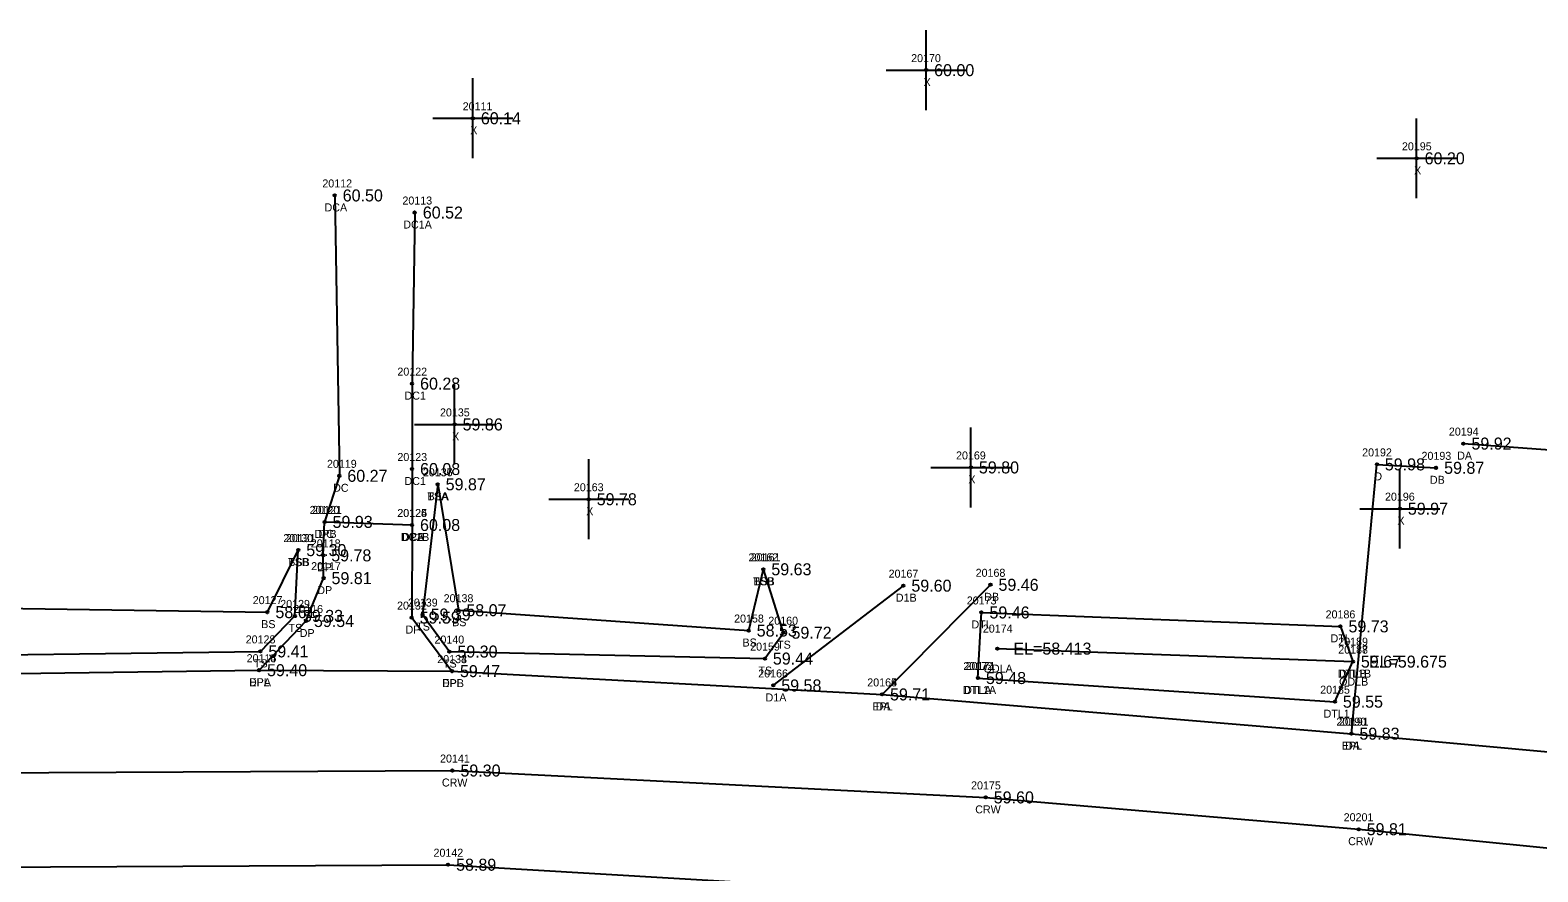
# Model space of a CAD drawing. Extents: x 2420351 to 2422725, y 845330 to 846558.
# Drawn here: x 2420630.1 to 2420818.7, y 845710.4 to 845815.6 of the extents above; entities that cross this region are included whole.
import ezdxf

# ---------------------------------------------------------------- set-up
doc = ezdxf.new("R2010")
doc.units = 0
for name, color, linetype in [('RD_DTM_BkLn1', 7, 'Continuous'), ('RD_DTM_BkLn2', 7, 'Continuous'), ('RD_DTM_BkLn_txCode', 7, 'Continuous'), ('RD_EX_Conc', 7, 'Continuous'), ('RD_EX_Conc_txCode', 7, 'Continuous'), ('RD_EX_Driveway', 7, 'Continuous'), ('RD_EX_Driveway_txCode', 7, 'Continuous'), ('RD_EX_H2O', 7, 'Continuous'), ('RD_EX_H2O_txCode', 7, 'Continuous'), ('RD_EX_Misc', 7, 'Continuous'), ('RD_EX_Misc_txCode', 7, 'Continuous'), ('RD_EX_Road', 7, 'Continuous'), ('RD_EX_Road_txCode', 7, 'Continuous'), ('RD_EX_TX_Conc_ELEV', 7, 'Continuous'), ('RD_EX_TX_Driveway_ELEV', 7, 'Continuous'), ('RD_EX_TX_H2O_ELEV', 7, 'Continuous'), ('RD_EX_TX_Misc_ELEV', 7, 'Continuous'), ('RD_EX_TX_Road_ELEV', 7, 'Continuous'), ('RD_HC_Survey_ELEV', 7, 'Continuous'), ('RD_HC_Survey_txCode', 7, 'Continuous'), ('RD_SMD_Locator', 7, 'Continuous')]:
    doc.layers.add(name, color=color, linetype=linetype)

msp = doc.modelspace()

# ---------------------------------------------------------------- linework, layer by layer
at = {"layer": 'RD_DTM_BkLn1'}
msp.add_lwpolyline([(2420378.71, 845690.53), (2420439.5, 845704.09), (2420489.95, 845712.49), (2420551.89, 845719.42), (2420551.95, 845719.57), (2420607.12, 845722.67), (2420682.92, 845723.04), (2420749.65, 845719.68), (2420796.31, 845715.7), (2420900.74, 845705.33), (2421018.16, 845694.11), (2421114.61, 845684.8), (2421175.74, 845680.1), (2421234.97, 845678.35), (2421292.42, 845679.46), (2421350.56, 845683.65), (2421414.53, 845692.12), (2421472.54, 845703.63), (2421533.08, 845718.31), (2421555.4, 845725.02), (2421609.81, 845741.71), (2421666.58, 845762.88), (2421744.67, 845798.22)], dxfattribs=at)
at = {"layer": 'RD_DTM_BkLn2'}
for points in [[(2420681.07, 845758.84), (2420679.19, 845742.55), (2420682.54, 845737.92), (2420722.01, 845737.04), (2420724.34, 845740.28), (2420721.82, 845748.21)], [(2420681.07, 845758.84), (2420683.66, 845743.09), (2420719.99, 845740.55), (2420721.82, 845748.21)], [(2420486.29, 845740.93), (2420484.7, 845732.95), (2420489.01, 845728.47), (2420550.73, 845734.95), (2420607.11, 845737.26), (2420658.89, 845737.94), (2420663.21, 845742.38), (2420663.63, 845750.61)], [(2420486.29, 845740.93), (2420490.14, 845734.65), (2420550.02, 845741.87), (2420606.87, 845743.63), (2420659.77, 845742.85), (2420663.63, 845750.61)]]:
    msp.add_lwpolyline(points, dxfattribs=at)
at = {"layer": 'RD_EX_Conc'}
for points in [[(2420668.19, 845794.97), (2420668.77, 845759.9), (2420666.92, 845754.14), (2420677.86, 845753.75)], [(2420678.21, 845792.83), (2420677.87, 845771.43), (2420677.87, 845760.75), (2420677.86, 845753.75)]]:
    msp.add_lwpolyline(points, dxfattribs=at)
at = {"layer": 'RD_EX_Driveway'}
for p, q in [((2420723.06, 845733.68), (2420739.34, 845746.16)), ((2420736.67, 845732.56), (2420750.24, 845746.27))]:
    msp.add_line(p, q, dxfattribs=at)
for points in [[(2420809.42, 845763.93), (2420862.38, 845760.08), (2420865.05, 845760.09), (2420893.89, 845756.85), (2420889.7, 845718.98)], [(2420795.4, 845727.65), (2420798.58, 845761.33), (2420806, 845760.9)], [(2420658.72, 845735.59), (2420664.59, 845741.74), (2420666.79, 845747.1), (2420666.75, 845749.95), (2420666.92, 845754.14)], [(2420677.86, 845753.75), (2420677.82, 845742.17), (2420682.86, 845735.47)]]:
    msp.add_lwpolyline(points, dxfattribs=at)
at = {"layer": 'RD_EX_H2O'}
msp.add_line((2420751.11, 845738.29), (2420795.58, 845736.66), dxfattribs=at)
for points in [[(2420748.67, 845734.61), (2420749.11, 845742.81), (2420794.03, 845741.07), (2420795.58, 845736.66)], [(2420748.67, 845734.61), (2420793.33, 845731.65), (2420795.58, 845736.66)]]:
    msp.add_lwpolyline(points, dxfattribs=at)
at = {"layer": 'RD_EX_Misc'}
for p, q in [((2420742.19, 845805.64), (2420742.19, 845815.64)), ((2420737.19, 845810.64), (2420747.19, 845810.64)), ((2420685.47, 845799.62), (2420685.47, 845809.62)), ((2420680.47, 845804.62), (2420690.47, 845804.62)), ((2420803.56, 845794.61), (2420803.56, 845804.61)), ((2420798.56, 845799.61), (2420808.56, 845799.61)), ((2420683.19, 845761.33), (2420683.19, 845771.33)), ((2420678.19, 845766.33), (2420688.19, 845766.33)), ((2420747.79, 845755.95), (2420747.79, 845765.95)), ((2420699.97, 845751.97), (2420699.97, 845761.97)), ((2420742.79, 845760.95), (2420752.79, 845760.95)), ((2420801.46, 845750.79), (2420801.46, 845760.79)), ((2420694.97, 845756.97), (2420704.97, 845756.97)), ((2420796.46, 845755.79), (2420806.46, 845755.79))]:
    msp.add_line(p, q, dxfattribs=at)
at = {"layer": 'RD_EX_Road'}
for points in [[(2420388.28, 845680.39), (2420441.29, 845692.04), (2420492.62, 845700.7), (2420553.92, 845707.41), (2420607.69, 845710.85), (2420682.38, 845711.26), (2420749.44, 845707.27), (2420795.12, 845703.44), (2420900.28, 845693.42), (2421017.17, 845682.19), (2421113.9, 845672.97), (2421174.87, 845668.16), (2421234.59, 845666.13), (2421293, 845667.25), (2421351.24, 845671.5), (2421419.82, 845681.17), (2421463.19, 845688.63), (2421558.82, 845713.18), (2421614.57, 845730.45), (2421670.73, 845751.42), (2421735.61, 845780.5), (2421750.75, 845787.87), (2421744.67, 845798.22), (2421739.21, 845808.11)], [(2420376.35, 845701.93), (2420403.68, 845709.11), (2420436.45, 845715.41), (2420465.85, 845720.8), (2420487.58, 845724.76), (2420551.29, 845731.53), (2420607.05, 845734.89), (2420658.72, 845735.59), (2420682.86, 845735.47), (2420736.67, 845732.56), (2420795.4, 845727.65), (2420889.7, 845718.98), (2420911.08, 845716.87), (2420953.91, 845713.71), (2420998.34, 845708.25), (2421018.47, 845706.55), (2421116.02, 845696.98), (2421176.98, 845692), (2421235.85, 845690.14), (2421292.32, 845691.44), (2421350.22, 845695.49), (2421412.35, 845704.28)]]:
    msp.add_lwpolyline(points, dxfattribs=at)
at = {"layer": 'RD_SMD_Locator'}
for centre in [(2420742.19, 845810.64), (2420685.47, 845804.62), (2420803.56, 845799.61), (2420668.19, 845794.97), (2420678.21, 845792.83), (2420677.87, 845771.43), (2420683.19, 845766.33), (2420809.42, 845763.93), (2420668.77, 845759.9), (2420677.87, 845760.75), (2420747.79, 845760.95), (2420798.58, 845761.33), (2420806, 845760.9), (2420681.07, 845758.84), (2420681.07, 845758.84), (2420699.97, 845756.97), (2420801.46, 845755.79), (2420666.92, 845754.14), (2420666.92, 845754.14), (2420677.86, 845753.75), (2420677.86, 845753.75), (2420677.86, 845753.75), (2420663.63, 845750.61), (2420663.63, 845750.61), (2420666.75, 845749.95), (2420721.82, 845748.21), (2420721.82, 845748.21), (2420666.79, 845747.1), (2420750.24, 845746.27), (2420739.34, 845746.16), (2420659.77, 845742.85), (2420679.19, 845742.55), (2420683.66, 845743.09), (2420749.11, 845742.81), (2420663.21, 845742.38), (2420664.59, 845741.74), (2420677.82, 845742.17), (2420794.03, 845741.07), (2420719.99, 845740.55), (2420724.34, 845740.28), (2420658.89, 845737.94), (2420682.54, 845737.92), (2420722.01, 845737.04), (2420751.11, 845738.29), (2420658.72, 845735.59), (2420658.72, 845735.59), (2420682.86, 845735.47), (2420682.86, 845735.47), (2420795.58, 845736.66), (2420795.58, 845736.66), (2420795.58, 845736.66), (2420723.06, 845733.68), (2420748.67, 845734.61), (2420748.67, 845734.61), (2420736.67, 845732.56), (2420736.67, 845732.56), (2420793.33, 845731.65), (2420795.4, 845727.65), (2420795.4, 845727.65), (2420682.92, 845723.04), (2420749.65, 845719.68), (2420796.31, 845715.7), (2420682.38, 845711.26)]:
    msp.add_circle(centre, 0.15, dxfattribs=at)

# ---------------------------------------------------------------- texts
at = {"layer": 'RD_DTM_BkLn_txCode'}
for s, p in [('20136', (2420679.21, 845759.84)), ('20137', (2420679.23, 845759.84)), ('TSA', (2420679.78, 845756.84)), ('BSA', (2420679.8, 845756.84)), ('20130', (2420661.76, 845751.61)), ('20131', (2420662.08, 845751.61)), ('20162', (2420719.96, 845749.21)), ('20161', (2420720.24, 845749.21)), ('TSB', (2420662.37, 845748.61)), ('BSB', (2420662.38, 845748.61)), ('TSB', (2420720.55, 845746.21)), ('BSB', (2420720.57, 845746.21)), ('20127', (2420657.93, 845743.85)), ('20139', (2420677.35, 845743.55)), ('20138', (2420681.82, 845744.09)), ('20129', (2420661.37, 845743.38)), ('BS', (2420658.99, 845740.85)), ('TS', (2420662.41, 845740.38)), ('TS', (2420678.39, 845740.55)), ('BS', (2420682.88, 845741.09)), ('20158', (2420718.16, 845741.55)), ('20160', (2420722.44, 845741.28)), ('20128', (2420657.05, 845738.94)), ('20140', (2420680.67, 845738.92)), ('BS', (2420719.21, 845738.55)), ('20159', (2420720.17, 845738.04)), ('TS', (2420723.54, 845738.28)), ('TS', (2420658.09, 845735.94)), ('TS', (2420681.74, 845735.92)), ('TS', (2420721.21, 845735.04))]:
    msp.add_text(s, height=1, dxfattribs=at).set_placement(p)
at = {"layer": 'RD_EX_Conc_txCode'}
for s, p in [('20112', (2420666.64, 845795.97)), ('DCA', (2420666.92, 845792.97)), ('20113', (2420676.66, 845793.83)), ('DC1A', (2420676.77, 845790.83)), ('20122', (2420676.03, 845772.43)), ('DC1', (2420676.92, 845769.43)), ('20119', (2420667.22, 845760.9)), ('20123', (2420676.03, 845761.75)), ('DC1', (2420676.92, 845758.75)), ('DC', (2420667.99, 845757.9)), ('20121', (2420665.37, 845755.14)), ('20124', (2420676.03, 845754.75)), ('20125', (2420676.03, 845754.75)), ('DC', (2420666.14, 845752.14)), ('DC1B', (2420676.45, 845751.75)), ('DCB', (2420676.61, 845751.75))]:
    msp.add_text(s, height=1, dxfattribs=at).set_placement(p)
at = {"layer": 'RD_EX_Driveway_txCode'}
for s, p in [('20194', (2420807.59, 845764.93)), ('20192', (2420796.74, 845762.33)), ('20193', (2420804.17, 845761.9)), ('DA', (2420808.63, 845761.93)), ('D', (2420798.27, 845759.33)), ('DB', (2420805.22, 845758.9)), ('20120', (2420665.05, 845755.14)), ('20126', (2420676.01, 845754.75)), ('DPB', (2420665.67, 845752.14)), ('DPA', (2420676.6, 845751.75)), ('20118', (2420665.2, 845750.95)), ('20117', (2420665.24, 845748.1)), ('DP', (2420665.97, 845747.95)), ('20167', (2420737.49, 845747.16)), ('20168', (2420748.38, 845747.27)), ('DP', (2420666.01, 845745.1)), ('D1B', (2420738.4, 845744.16)), ('DB', (2420749.46, 845744.27)), ('20116', (2420663.01, 845742.74)), ('20132', (2420675.99, 845743.17)), ('DP', (2420663.81, 845739.74)), ('DP', (2420677.05, 845740.17)), ('20115', (2420657.17, 845736.59)), ('20133', (2420681.02, 845736.47)), ('20166', (2420721.18, 845734.68)), ('DPA', (2420657.46, 845733.59)), ('DPB', (2420681.61, 845733.47)), ('20165', (2420734.82, 845733.56)), ('D1A', (2420722.1, 845731.68)), ('DA', (2420735.88, 845730.56)), ('20191', (2420793.84, 845728.65)), ('DA', (2420794.6, 845725.65))]:
    msp.add_text(s, height=1, dxfattribs=at).set_placement(p)
at = {"layer": 'RD_EX_H2O_txCode'}
for s, p in [('20173', (2420747.27, 845743.81)), ('20186', (2420792.17, 845742.07)), ('DTL', (2420747.86, 845740.81)), ('20174', (2420749.28, 845740.29)), ('DTL', (2420792.79, 845739.07)), ('20189', (2420793.75, 845738.66)), ('20187', (2420793.75, 845737.66)), ('20188', (2420793.75, 845737.66)), ('20172', (2420746.84, 845735.61)), ('20171', (2420747.12, 845735.61)), ('ODLA', (2420749.38, 845735.29)), ('DTL1B', (2420793.7, 845734.66)), ('DTLB', (2420793.86, 845734.66)), ('DTL1A', (2420746.78, 845732.61)), ('DTLA', (2420746.94, 845732.61)), ('20185', (2420791.49, 845732.65)), ('ODLB', (2420793.86, 845733.66)), ('DTL1', (2420791.92, 845729.65))]:
    msp.add_text(s, height=1, dxfattribs=at).set_placement(p)
at = {"layer": 'RD_EX_Misc_txCode'}
for s, p in [('20170', (2420740.31, 845811.64)), ('X', (2420741.87, 845808.64)), ('20111', (2420684.2, 845805.62)), ('X', (2420685.15, 845802.62)), ('20195', (2420801.72, 845800.61)), ('X', (2420803.24, 845797.61)), ('20135', (2420681.36, 845767.33)), ('X', (2420682.88, 845764.33)), ('20169', (2420745.93, 845761.95)), ('X', (2420747.47, 845758.95)), ('20163', (2420698.11, 845757.97)), ('20196', (2420799.6, 845756.79)), ('X', (2420699.66, 845754.97)), ('X', (2420801.15, 845753.79))]:
    msp.add_text(s, height=1, dxfattribs=at).set_placement(p)
at = {"layer": 'RD_EX_Road_txCode'}
for s, p in [('20114', (2420657.17, 845736.59)), ('20134', (2420681.02, 845736.47)), ('EPL', (2420657.52, 845733.59)), ('EPL', (2420681.65, 845733.47)), ('20164', (2420734.82, 845733.56)), ('EPL', (2420735.47, 845730.56)), ('20190', (2420793.52, 845728.65)), ('EPL', (2420794.19, 845725.65)), ('20142', (2420680.55, 845712.26))]:
    msp.add_text(s, height=1, dxfattribs=at).set_placement(p)
at = {"layer": 'RD_EX_TX_Conc_ELEV'}
for s, p in [('60.50', (2420669.19, 845794.22)), ('60.52', (2420679.21, 845792.08)), ('60.28', (2420678.87, 845770.68)), ('60.08', (2420678.87, 845760)), ('60.27', (2420669.77, 845759.15)), ('59.93', (2420667.92, 845753.39)), ('60.08', (2420678.86, 845753)), ('60.08', (2420678.86, 845753))]:
    msp.add_text(s, height=1.5, dxfattribs=at).set_placement(p)
at = {"layer": 'RD_EX_TX_Driveway_ELEV'}
for s, p in [('59.92', (2420810.42, 845763.18)), ('59.98', (2420799.58, 845760.58)), ('59.87', (2420807, 845760.15)), ('59.93', (2420667.92, 845753.39)), ('60.08', (2420678.86, 845753)), ('59.78', (2420667.75, 845749.2)), ('59.81', (2420667.79, 845746.35)), ('59.60', (2420740.34, 845745.41)), ('59.46', (2420751.24, 845745.52)), ('59.59', (2420678.82, 845741.42)), ('59.54', (2420665.59, 845740.99)), ('59.40', (2420659.72, 845734.84)), ('59.47', (2420683.86, 845734.72)), ('59.58', (2420724.06, 845732.93)), ('59.71', (2420737.67, 845731.81)), ('59.83', (2420796.4, 845726.9))]:
    msp.add_text(s, height=1.5, dxfattribs=at).set_placement(p)
at = {"layer": 'RD_EX_TX_H2O_ELEV'}
for s, p in [('59.46', (2420750.11, 845742.06)), ('59.73', (2420795.03, 845740.32)), ('EL=58.413', (2420753.11, 845737.54)), ('59.67', (2420796.58, 845735.91)), ('59.67', (2420796.58, 845735.91)), ('EL=59.675', (2420797.58, 845735.91)), ('59.48', (2420749.67, 845733.86)), ('59.48', (2420749.67, 845733.86)), ('59.55', (2420794.33, 845730.9))]:
    msp.add_text(s, height=1.5, dxfattribs=at).set_placement(p)
at = {"layer": 'RD_EX_TX_Misc_ELEV'}
for s, p in [('60.00', (2420743.19, 845809.89)), ('60.14', (2420686.47, 845803.87)), ('60.20', (2420804.56, 845798.86)), ('59.86', (2420684.19, 845765.58)), ('59.80', (2420748.79, 845760.2)), ('59.87', (2420682.07, 845758.09)), ('59.87', (2420682.07, 845758.09)), ('59.78', (2420700.97, 845756.22)), ('59.97', (2420802.46, 845755.04)), ('59.30', (2420664.63, 845749.86)), ('59.30', (2420664.63, 845749.86)), ('59.63', (2420722.82, 845747.46)), ('59.63', (2420722.82, 845747.46)), ('58.61', (2420660.77, 845742.1)), ('59.33', (2420664.21, 845741.63)), ('59.39', (2420680.19, 845741.8)), ('58.07', (2420684.66, 845742.34)), ('58.53', (2420720.99, 845739.8)), ('59.72', (2420725.34, 845739.53)), ('59.41', (2420659.89, 845737.19)), ('59.30', (2420683.54, 845737.17)), ('59.44', (2420723.01, 845736.29))]:
    msp.add_text(s, height=1.5, dxfattribs=at).set_placement(p)
at = {"layer": 'RD_EX_TX_Road_ELEV'}
for s, p in [('59.40', (2420659.72, 845734.84)), ('59.47', (2420683.86, 845734.72)), ('59.71', (2420737.67, 845731.81)), ('59.83', (2420796.4, 845726.9)), ('58.89', (2420683.38, 845710.51))]:
    msp.add_text(s, height=1.5, dxfattribs=at).set_placement(p)
at = {"layer": 'RD_HC_Survey_ELEV'}
for s, p in [('59.30', (2420683.92, 845722.29)), ('59.60', (2420750.65, 845718.93)), ('59.81', (2420797.31, 845714.95))]:
    msp.add_text(s, height=1.5, dxfattribs=at).set_placement(p)
at = {"layer": 'RD_HC_Survey_txCode'}
for s, p in [('20141', (2420681.37, 845724.04)), ('CRW', (2420681.6, 845721.04)), ('20175', (2420747.81, 845720.68)), ('CRW', (2420748.33, 845717.68)), ('20201', (2420794.43, 845716.7)), ('CRW', (2420794.99, 845713.7))]:
    msp.add_text(s, height=1, dxfattribs=at).set_placement(p)

doc.saveas('drawing.dxf')
